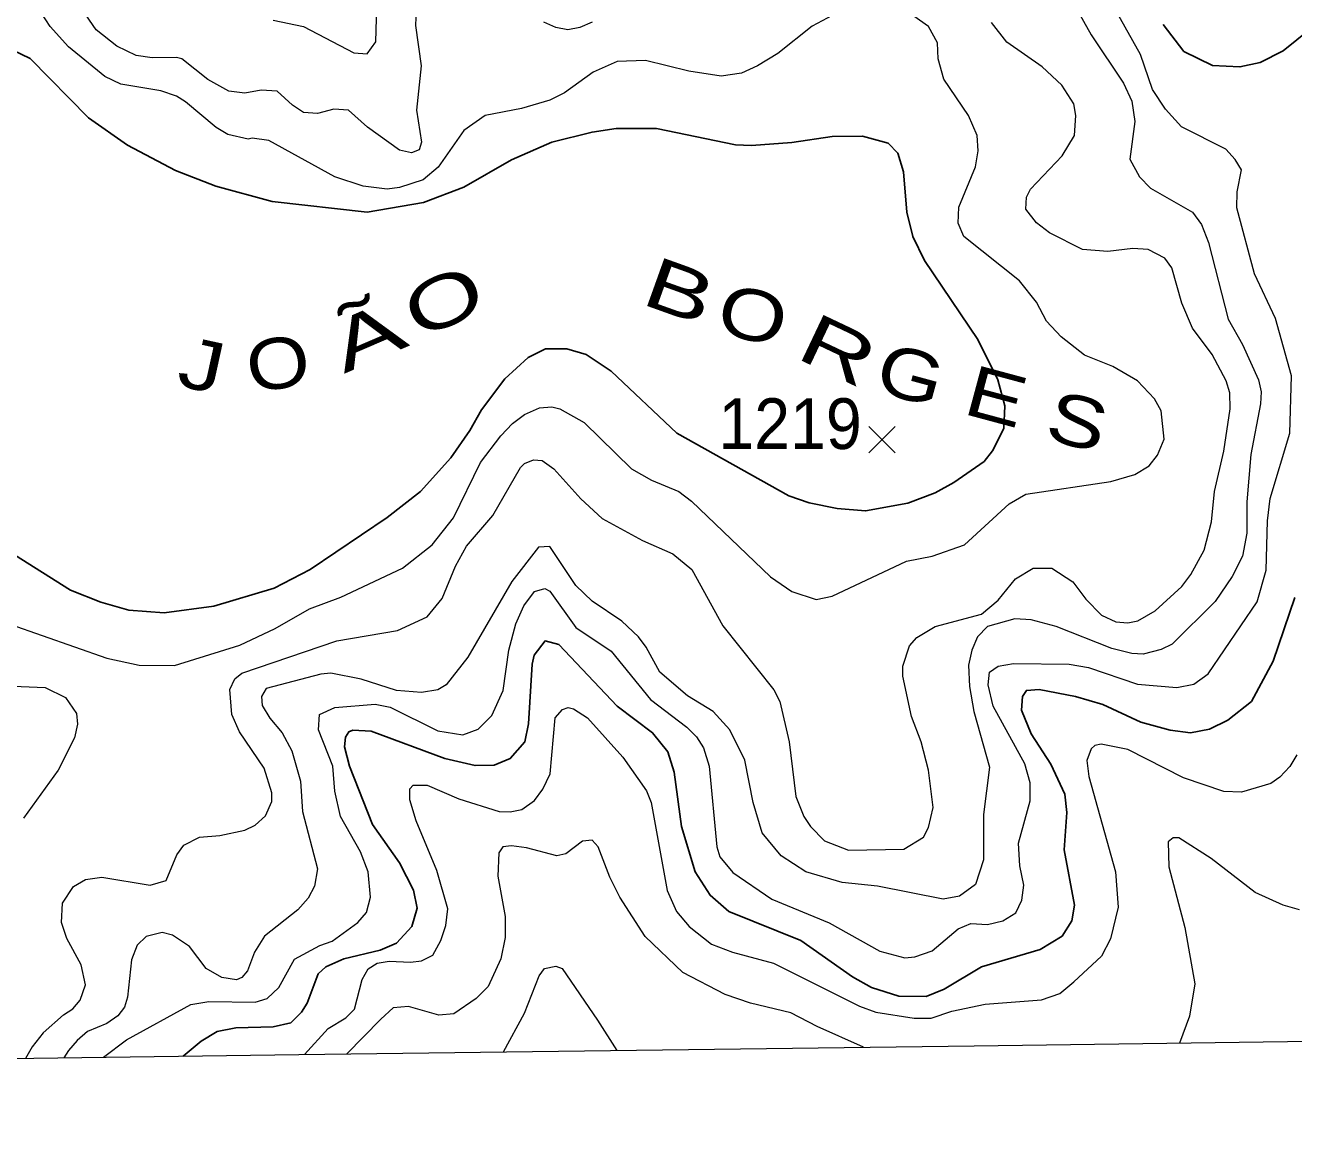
# Model space of a CAD drawing. Extents: x 265 to 291.4, y 7731.5 to 7759.6.
# Drawn here: x 273.421 to 275.42, y 7731.544 to 7733.283 of the extents above; entities that cross this region are included whole.
import ezdxf
from ezdxf.enums import TextEntityAlignment as Align

# ---------------------------------------------------------------- set-up
doc = ezdxf.new("R2010")
doc.units = 0
doc.header["$LTSCALE"] = 0.032
for name, color, linetype, lineweight in [('1', 7, 'Continuous', 25), ('2', 7, 'Continuous', 13), ('21', 7, 'Continuous', 25), ('61', 7, 'Continuous', 13), ('63', 7, 'Continuous', 25)]:
    doc.layers.add(name, color=color, linetype=linetype, lineweight=lineweight)

msp = doc.modelspace()

# ---------------------------------------------------------------- linework, layer by layer
at = {"layer": '1'}
for points in [[(275.2147, 7733.2838), (275.2473, 7733.2416), (275.2927, 7733.2193), (275.3356, 7733.217), (275.3674, 7733.2241), (275.404, 7733.2424), (275.4661, 7733.2925)], [(273.4034, 7732.4477), (273.4917, 7732.392), (273.5394, 7732.3729), (273.584, 7732.3602), (273.6397, 7732.3562), (273.7176, 7732.3666), (273.8131, 7732.3952), (273.8695, 7732.4247), (273.9913, 7732.5066), (274.0438, 7732.5472), (274.0915, 7732.6005), (274.1217, 7732.6434), (274.14, 7732.6761), (274.1766, 7732.7254), (274.2132, 7732.7588), (274.241, 7732.7723), (274.2745, 7732.7723), (274.3047, 7732.7635), (274.3444, 7732.7373), (274.4479, 7732.6394), (274.6245, 7732.5408), (274.6563, 7732.5297), (274.7008, 7732.5209), (274.7454, 7732.5169), (274.8122, 7732.5289), (274.8552, 7732.5456), (274.8846, 7732.5615), (274.9323, 7732.5949), (274.9458, 7732.6116), (274.9633, 7732.6466), (274.9652, 7732.6828), (274.9538, 7732.7238), (274.9227, 7732.7874), (274.8384, 7732.9115), (274.8201, 7732.9497), (274.8106, 7732.9879), (274.805, 7733.0515), (274.7963, 7733.0809), (274.7812, 7733.0968), (274.7406, 7733.108), (274.6929, 7733.1072), (274.6292, 7733.0976), (274.5656, 7733.0929), (274.5401, 7733.0944), (274.416, 7733.1199), (274.3524, 7733.1199), (274.3142, 7733.1143), (274.2506, 7733.0984), (274.1869, 7733.0706), (274.1122, 7733.0276), (274.0485, 7733.003), (273.9594, 7732.9879), (273.8099, 7733.0046), (273.7208, 7733.0292), (273.6572, 7733.0539), (273.5816, 7733.0936), (273.5203, 7733.1366), (273.428, 7733.2305), (273.3867, 7733.2504)], [(275.4223, 7732.3801), (275.3881, 7732.2799), (275.3539, 7732.2163), (275.3165, 7732.1868), (275.2879, 7732.1725), (275.2577, 7732.1669), (275.2259, 7732.1709), (275.1797, 7732.1836), (275.1193, 7732.2115), (275.0763, 7732.2242), (275.019, 7732.2353), (274.9991, 7732.2337), (274.9928, 7732.2242), (274.9912, 7732.2027), (275.0063, 7732.1654), (275.0373, 7732.1176), (275.0596, 7732.0699), (275.0628, 7732.0413), (275.0588, 7731.9824), (275.0747, 7731.8949), (275.0707, 7731.8702), (275.0556, 7731.8463), (275.0206, 7731.8249), (274.9283, 7731.7978), (274.8695, 7731.7628), (274.8408, 7731.7509), (274.7979, 7731.7517), (274.7549, 7731.7652), (274.7247, 7731.7819), (274.6436, 7731.8392), (274.5298, 7731.8853), (274.5003, 7731.9108), (274.4765, 7731.9474), (274.455, 7732.019), (274.4439, 7732.1049), (274.4335, 7732.1367), (274.4097, 7732.1669), (274.354, 7732.2091), (274.2617, 7732.3061), (274.2402, 7732.3117), (274.2227, 7732.2894), (274.2195, 7732.2751), (274.214, 7732.1813), (274.2084, 7732.1526), (274.1853, 7732.1264), (274.1599, 7732.116), (274.1297, 7732.1152), (274.0819, 7732.1263), (273.9658, 7732.1693), (273.9372, 7732.1709), (273.9308, 7732.1685), (273.9252, 7732.1598), (273.9236, 7732.1447), (273.9316, 7732.1144), (273.9682, 7732.0222), (274.0103, 7731.9617), (274.0326, 7731.9188), (274.0382, 7731.8901), (274.0302, 7731.8615), (274.0056, 7731.8352), (273.9801, 7731.8241), (273.9228, 7731.8105), (273.8942, 7731.7978), (273.8823, 7731.7867), (273.8648, 7731.7406), (273.856, 7731.7262), (273.8393, 7731.7095), (273.8115, 7731.7032), (273.7526, 7731.7016)], [(273.7526, 7731.7016), (273.7232, 7731.6957), (273.6977, 7731.6804), (273.6697, 7731.6568)]]:
    msp.add_lwpolyline(points, dxfattribs=at)
at = {"layer": '2'}
msp.add_line((273.5437, 7731.6552), (273.5803, 7731.6828), dxfattribs=at)
for points in [[(273.5803, 7731.6828), (273.6815, 7731.7382), (273.7097, 7731.7429), (273.7828, 7731.7421), (273.8019, 7731.7477), (273.8202, 7731.7652), (273.8449, 7731.8098), (273.8847, 7731.8312), (273.9045, 7731.8384), (273.9451, 7731.8678), (273.9586, 7731.8837), (273.965, 7731.9076), (273.961, 7731.9474), (273.9491, 7731.9792), (273.9173, 7732.0349), (273.9085, 7732.0747), (273.9053, 7732.1144), (273.8831, 7732.1717), (273.8846, 7732.1956), (273.9085, 7732.2067), (273.9722, 7732.2123), (273.996, 7732.2075), (274.0708, 7732.1701), (274.1106, 7732.1637), (274.1344, 7732.1725), (274.1559, 7732.194), (274.1742, 7732.2338), (274.183, 7732.2974), (274.1941, 7732.3388), (274.2068, 7732.3674), (274.2235, 7732.3897), (274.2395, 7732.3944), (274.2474, 7732.3905), (274.2888, 7732.3332), (274.3445, 7732.2958), (274.4065, 7732.2194), (274.4638, 7732.1757), (274.4789, 7732.1606), (274.49, 7732.1431), (274.4988, 7732.1144), (274.5107, 7731.9872), (274.5155, 7731.9713), (274.5362, 7731.9466), (274.5974, 7731.9044), (274.6881, 7731.867), (274.7677, 7731.8225), (274.8074, 7731.8121), (274.8233, 7731.8137), (274.8504, 7731.8233), (274.8917, 7731.8575), (274.9116, 7731.8662), (274.9379, 7731.8646), (274.9618, 7731.8702), (274.9824, 7731.8829), (274.992, 7731.9028), (274.9952, 7731.9267), (274.9888, 7731.9569), (274.9864, 7731.9927), (275.0051, 7732.0595), (275.0051, 7732.088), (274.9965, 7732.1179), (274.9467, 7732.2089), (274.9387, 7732.2428), (274.941, 7732.2627), (274.9543, 7732.272), (274.9789, 7732.276), (275.0665, 7732.2754), (275.0971, 7732.27), (275.1741, 7732.2435), (275.2362, 7732.2381), (275.2628, 7732.2434), (275.2854, 7732.26), (275.3631, 7732.3736), (275.377, 7732.4234), (275.3794, 7732.5012), (275.3834, 7732.5364), (275.4146, 7732.6394), (275.4169, 7732.7297), (275.3917, 7732.8201), (275.3585, 7732.8905), (275.3309, 7732.9948), (275.3316, 7733.02), (275.3382, 7733.0546), (275.3283, 7733.0712), (275.3137, 7733.0871), (275.2436, 7733.1224), (275.2184, 7733.1503), (275.1978, 7733.1815), (275.1792, 7733.2366), (275.1137, 7733.3536)], [(273.8115, 7733.2909), (273.8592, 7733.2806), (273.9388, 7733.2392), (273.9594, 7733.2376), (273.973, 7733.2568), (273.9761, 7733.349)], [(274.6929, 7733.2981), (274.6611, 7733.2814), (274.607, 7733.2384), (274.5751, 7733.2186), (274.5497, 7733.2074), (274.5179, 7733.2026), (274.467, 7733.2106), (274.3985, 7733.2273), (274.354, 7733.2257), (274.3158, 7733.209), (274.2705, 7733.1764), (274.2474, 7733.1645), (274.2029, 7733.1517), (274.1456, 7733.1406), (274.1122, 7733.1167), (274.0716, 7733.0587), (274.0477, 7733.0388), (274.0104, 7733.0268), (273.9913, 7733.0245), (273.9531, 7733.0292), (273.9085, 7733.0436), (273.8043, 7733.1008), (273.7781, 7733.1048), (273.7717, 7733.1032), (273.7399, 7733.1104), (273.7216, 7733.1215), (273.6731, 7733.1621), (273.6587, 7733.1708), (273.6341, 7733.1796), (273.5712, 7733.1899), (273.5458, 7733.2019), (273.4885, 7733.2488), (273.4599, 7733.2806), (273.4392, 7733.3124)], [(273.7669, 7733.1756), (273.7415, 7733.1788), (273.7081, 7733.1971), (273.6675, 7733.2297), (273.6587, 7733.2321), (273.6206, 7733.2313), (273.5951, 7733.2353), (273.5649, 7733.2496), (273.5323, 7733.2758), (273.51, 7733.3077)], [(274.0374, 7733.3204), (274.0358, 7733.2822), (274.0445, 7733.2186), (274.0374, 7733.1486), (274.0453, 7733.0984), (274.0414, 7733.0865), (274.0294, 7733.0817), (274.0104, 7733.0857), (273.9602, 7733.1223), (273.93, 7733.1486), (273.9069, 7733.1502)], [(275.0771, 7733.3108), (275.1009, 7733.2679), (275.1519, 7733.1915), (275.1654, 7733.1629), (275.1702, 7733.1311), (275.1622, 7733.0714), (275.1773, 7733.0436), (275.1948, 7733.0261), (275.2609, 7732.9879), (275.2752, 7732.9688), (275.2863, 7732.9402), (275.3173, 7732.8192), (275.3396, 7732.7795), (275.3651, 7732.7238), (275.369, 7732.7047), (275.3682, 7732.6856), (275.3531, 7732.606), (275.3468, 7732.5313), (275.3468, 7732.482), (275.3396, 7732.4454), (275.3237, 7732.4135), (275.2966, 7732.3738), (275.229, 7732.3069), (275.2115, 7732.2982), (275.1829, 7732.291), (275.1654, 7732.2918), (275.1336, 7732.2998), (275.0461, 7732.3348), (275.0063, 7732.3451), (274.9808, 7732.3467), (274.9379, 7732.3348), (274.922, 7732.3181), (274.9132, 7732.2974), (274.9076, 7732.2735), (274.9092, 7732.2401), (274.9164, 7732.2004), (274.9411, 7732.1128), (274.9315, 7732.0381)], [(273.656, 7732.2732), (273.759, 7732.3053), (273.8147, 7732.3316), (273.8687, 7732.3626), (273.9181, 7732.3809), (274.0151, 7732.4263), (274.0621, 7732.4636), (274.0955, 7732.5058), (274.1384, 7732.5933), (274.1702, 7732.6355), (274.1885, 7732.6546), (274.2076, 7732.6689), (274.2315, 7732.6792), (274.2506, 7732.6808), (274.2633, 7732.6776), (274.3015, 7732.6562), (274.3763, 7732.583), (274.4081, 7732.5655), (274.451, 7732.5472), (274.4709, 7732.5321), (274.5958, 7732.4127), (274.6292, 7732.3897), (274.6674, 7732.3769), (274.6929, 7732.3825), (274.8098, 7732.4374), (274.8504, 7732.4454), (274.9013, 7732.4636), (274.9721, 7732.5281), (274.9983, 7732.5432), (275.132, 7732.5631), (275.1702, 7732.5742), (275.1924, 7732.5877), (275.206, 7732.6045), (275.2163, 7732.6299), (275.2115, 7732.6745), (275.2012, 7732.6936), (275.1741, 7732.7222), (275.1352, 7732.7445), (275.0906, 7732.7627), (275.054, 7732.7914), (275.0309, 7732.8161), (275.015, 7732.8463), (274.988, 7732.8797), (274.9005, 7732.9497), (274.8917, 7732.9704), (274.8925, 7732.9958), (274.9188, 7733.0595), (274.9228, 7733.0849), (274.9212, 7733.1088), (274.9076, 7733.1406), (274.8687, 7733.1979), (274.8599, 7733.2297), (274.8591, 7733.2552), (274.8448, 7733.2806), (274.8217, 7733.2973)], [(274.3142, 7733.2878), (274.2951, 7733.279), (274.276, 7733.2758), (274.257, 7733.279), (274.2379, 7733.2878)], [(275.0389, 7732.4263), (275.0723, 7732.4048), (275.093, 7732.3777), (275.1177, 7732.3523), (275.1399, 7732.3419), (275.159, 7732.3403), (275.1749, 7732.3435), (275.202, 7732.3594), (275.2441, 7732.3976), (275.2585, 7732.4167), (275.2791, 7732.4549), (275.2911, 7732.4995), (275.2958, 7732.5472), (275.3102, 7732.6108), (275.3205, 7732.6776), (275.3197, 7732.7031), (275.3141, 7732.7222), (275.2919, 7732.7636), (275.2608, 7732.8049), (275.2441, 7732.8447), (275.2282, 7732.9004), (275.2171, 7732.9155), (275.1909, 7732.929), (275.167, 7732.9306), (275.1272, 7732.9258), (275.0874, 7732.929), (275.0357, 7732.9553), (275.015, 7732.9712), (274.9983, 7732.9927), (274.9991, 7733.0117), (275.0055, 7733.0245), (275.0556, 7733.077), (275.0747, 7733.1088), (275.0771, 7733.1406), (275.0739, 7733.1589), (275.0548, 7733.1883), (275.0238, 7733.217), (274.9681, 7733.2559), (274.9442, 7733.287)], [(273.9069, 7733.1502), (273.8815, 7733.1438), (273.8592, 7733.1454), (273.8417, 7733.1565), (273.8178, 7733.1788), (273.7924, 7733.1804), (273.7669, 7733.1756)], [(273.4487, 7731.6936), (273.4806, 7731.7223), (273.4957, 7731.7318), (273.5068, 7731.7453), (273.5156, 7731.7692), (273.5084, 7731.801), (273.4861, 7731.8424), (273.4774, 7731.8678), (273.479, 7731.8981), (273.4965, 7731.9243), (273.5156, 7731.9354), (273.541, 7731.9394), (273.6174, 7731.9267), (273.6428, 7731.9339), (273.6595, 7731.9744), (273.6707, 7731.9895), (273.6953, 7732.0023), (273.7272, 7732.0047), (273.7669, 7732.0134), (273.7828, 7732.0214), (273.7995, 7732.0357), (273.8091, 7732.0588), (273.8091, 7732.0723), (273.7972, 7732.1113), (273.7582, 7732.1685), (273.7462, 7732.1956), (273.7431, 7732.2354), (273.751, 7732.252), (273.7622, 7732.2608), (273.9117, 7732.3117), (274.0072, 7732.3284), (274.0541, 7732.3499), (274.078, 7732.3785), (274.0986, 7732.4295), (274.1161, 7732.4613), (274.1575, 7732.5098), (274.2012, 7732.5854), (274.2076, 7732.5917), (274.222, 7732.5973), (274.2355, 7732.5965), (274.2538, 7732.583), (274.2967, 7732.536), (274.3301, 7732.505), (274.3938, 7732.47), (274.4415, 7732.4493), (274.4717, 7732.4247), (274.5202, 7732.3356), (274.6006, 7732.2346), (274.6101, 7732.2163), (274.6252, 7732.1526), (274.6356, 7732.0667), (274.6483, 7732.0349), (274.6587, 7732.019), (274.6809, 7731.9967), (274.7183, 7731.9816), (274.8058, 7731.9832), (274.8368, 7732.0023), (274.8448, 7732.0174), (274.852, 7732.0492), (274.8448, 7732.1081), (274.8329, 7732.1526), (274.8178, 7732.1924), (274.8042, 7732.256), (274.8042, 7732.2719), (274.8146, 7732.3038), (274.8265, 7732.3173), (274.8551, 7732.3348), (274.9283, 7732.3539), (274.9546, 7732.3761), (274.9816, 7732.4096), (275.0095, 7732.4263), (275.0389, 7732.4263)], [(274.7088, 7731.9307), (274.6515, 7731.9474), (274.6125, 7731.9728), (274.5823, 7732.0094), (274.568, 7732.0572), (274.5552, 7732.124), (274.5314, 7732.1717), (274.5051, 7732.2003), (274.4646, 7732.225), (274.4208, 7732.2624), (274.3993, 7732.3022), (274.3874, 7732.3181), (274.3611, 7732.3427), (274.3142, 7732.3745), (274.2888, 7732.3992), (274.2474, 7732.4605), (274.2299, 7732.4597), (274.1877, 7732.4056), (274.1185, 7732.2863), (274.0843, 7732.2425), (274.0708, 7732.2345), (274.0454, 7732.2306), (274.0056, 7732.2338), (273.9499, 7732.2513), (273.9022, 7732.2608), (273.8863, 7732.2592), (273.8003, 7732.2369), (273.7932, 7732.2242), (273.794, 7732.2099), (273.8059, 7732.19), (273.8258, 7732.1669), (273.8409, 7732.1383), (273.8544, 7732.0906), (273.8576, 7732.0428), (273.8815, 7731.9522), (273.8767, 7731.9251), (273.8664, 7731.906), (273.8504, 7731.8877), (273.7979, 7731.8464), (273.782, 7731.8209), (273.7709, 7731.7915), (273.7622, 7731.7811), (273.7534, 7731.7771), (273.7303, 7731.7811), (273.7057, 7731.7954), (273.6794, 7731.8297), (273.6524, 7731.8479), (273.6365, 7731.8519), (273.611, 7731.8455), (273.5967, 7731.832), (273.5879, 7731.809), (273.5816, 7731.7501), (273.5768, 7731.7342), (273.5665, 7731.7207), (273.549, 7731.7087), (273.5187, 7731.696), (273.5025, 7731.6816), (273.4886, 7731.6657), (273.4813, 7731.6544)], [(273.3962, 7732.338), (273.549, 7732.2847), (273.5999, 7732.2735), (273.656, 7732.2732)], [(273.3756, 7732.2417), (273.4519, 7732.2385), (273.4837, 7732.2226), (273.5012, 7732.1972), (273.5028, 7732.1805), (273.4981, 7732.159), (273.4726, 7732.1081), (273.4177, 7732.0325)], [(273.8609, 7731.6594), (273.8982, 7731.7008), (273.926, 7731.7175), (273.9395, 7731.731), (273.9515, 7731.7779), (273.961, 7731.7947), (273.9754, 7731.8034), (273.9944, 7731.8066), (274.0279, 7731.805), (274.0454, 7731.8074), (274.0629, 7731.8161), (274.0756, 7731.8392), (274.0835, 7731.8631), (274.0867, 7731.8893), (274.0695, 7731.9496), (274.0369, 7732.028), (274.027, 7732.0612), (274.027, 7732.0785), (274.0323, 7732.0845), (274.0542, 7732.0845), (274.104, 7732.0626), (274.1678, 7732.0426), (274.185, 7732.042), (274.2036, 7732.0459), (274.2235, 7732.0599), (274.2368, 7732.0778), (274.2481, 7732.1024), (274.2558, 7732.1907), (274.2677, 7732.2034), (274.2764, 7732.2067), (274.285, 7732.2047), (274.3069, 7732.1907), (274.3627, 7732.1283), (274.3999, 7732.0752), (274.4072, 7732.0572), (274.4324, 7731.9184), (274.4473, 7731.8852), (274.4673, 7731.8613), (274.5025, 7731.8334), (274.5357, 7731.8207), (274.6001, 7731.8035), (274.7359, 7731.7357), (274.7618, 7731.7264), (274.8222, 7731.7171), (274.8488, 7731.7171), (274.8813, 7731.7277), (274.9338, 7731.739), (275.0231, 7731.7456), (275.0517, 7731.7556), (275.0736, 7731.7742)], [(275.4255, 7732.1319), (275.4144, 7732.1137), (275.3988, 7732.0971), (275.3842, 7732.0871), (275.3384, 7732.0732), (275.3105, 7732.0745), (275.2468, 7732.0958), (275.1591, 7732.1403), (275.1169, 7732.1489), (275.107, 7732.1469), (275.101, 7732.1416), (275.0944, 7732.123), (275.0977, 7732.0978), (275.1395, 7731.9477), (275.1438, 7731.8919), (275.1318, 7731.8421), (275.1172, 7731.8148), (275.0736, 7731.7742)], [(274.9315, 7732.0381), (274.9315, 7731.9665), (274.9188, 7731.9275), (274.8933, 7731.9092), (274.8679, 7731.9044), (274.7645, 7731.9251), (274.7088, 7731.9307)], [(274.7424, 7731.6711), (274.669, 7731.7036), (274.6276, 7731.7254), (274.564, 7731.7406), (274.5242, 7731.7541), (274.4574, 7731.7891), (274.3977, 7731.8456), (274.358, 7731.9076), (274.3421, 7731.9394), (274.3238, 7731.9872), (274.3142, 7731.9975), (274.2991, 7731.9959), (274.2729, 7731.976), (274.2585, 7731.9728), (274.2108, 7731.9856), (274.1869, 7731.9887), (274.1734, 7731.9872), (274.167, 7731.9776), (274.1655, 7731.941), (274.1774, 7731.8774), (274.1774, 7731.844), (274.1702, 7731.8106), (274.1503, 7731.7668), (274.1313, 7731.7477), (274.0963, 7731.7238), (274.0724, 7731.7215), (274.0247, 7731.735), (274.0008, 7731.7334), (273.9809, 7731.7151), (273.9272, 7731.6603)], [(275.4295, 7731.8877), (275.404, 7731.8949), (275.3595, 7731.9148), (275.2903, 7731.9689), (275.2394, 7732.0015), (275.2306, 7732.0015), (275.2227, 7731.9951), (275.2235, 7731.9553), (275.2489, 7731.8599), (275.2648, 7731.7708), (275.2561, 7731.7199), (275.2403, 7731.6776)], [(274.1745, 7731.6635), (274.2076, 7731.7247), (274.2307, 7731.7835), (274.2394, 7731.7954), (274.257, 7731.7986), (274.2673, 7731.7954), (274.323, 7731.7135), (274.3531, 7731.6659)], [(273.4487, 7731.6936), (273.4311, 7731.6714), (273.4207, 7731.6535)]]:
    msp.add_lwpolyline(points, dxfattribs=at)
at = {"layer": '21'}
for p, q in [((274.7508, 7732.6498), (274.792, 7732.6086)), ((274.792, 7732.6498), (274.7508, 7732.6086))]:
    msp.add_line(p, q, dxfattribs=at)
at = {"layer": '63', "lineweight": 13}
msp.add_lwpolyline([(265.3348, 7731.5442), (265.8671, 7731.5515), (266.3994, 7731.5588), (266.9318, 7731.5661), (267.4641, 7731.5734), (267.9964, 7731.5806), (268.5287, 7731.5879), (269.061, 7731.5951), (269.5934, 7731.6023), (270.1257, 7731.6095), (270.658, 7731.6166), (271.1903, 7731.6238), (271.7226, 7731.6309), (272.2549, 7731.638), (272.7872, 7731.6451), (273.3195, 7731.6522), (273.8519, 7731.6593), (274.3842, 7731.6663), (274.9165, 7731.6734), (275.4488, 7731.6804), (275.9811, 7731.6874), (276.5134, 7731.6944), (277.0457, 7731.7013)], dxfattribs=at)

# ---------------------------------------------------------------- texts
at = {"layer": '61'}
for s, rotation, width, p in [('B', 340.278, 1.5, (274.4391, 7732.8264)), ('O', 24.473, 1.5, (274.0969, 7732.8116)), ('O', 346.748, 1.3, (274.5586, 7732.7867)), ('Ã', 23.308, 1.6, (273.9754, 7732.7555)), ('R', 334.642, 1.5, (274.6853, 7732.7344)), ('J', 347.606, 1.3, (273.6906, 7732.7078)), ('O', 8.849, 1.2, (273.825, 7732.7102)), ('G', 344.864, 1.25, (274.8064, 7732.6929)), ('E', 344.945, 1.3, (274.9412, 7732.6588)), ('S', 345.563, 1.3, (275.0697, 7732.6194))]:
    msp.add_text(s, height=0.08, rotation=rotation, dxfattribs=dict(at, width=width)).set_placement(p, align=Align.CENTER)
at = {"layer": '61', "width": 0.95}
msp.add_text('1219', height=0.08, dxfattribs=at).set_placement((274.6264, 7732.6145), align=Align.CENTER)

doc.saveas('drawing.dxf')
